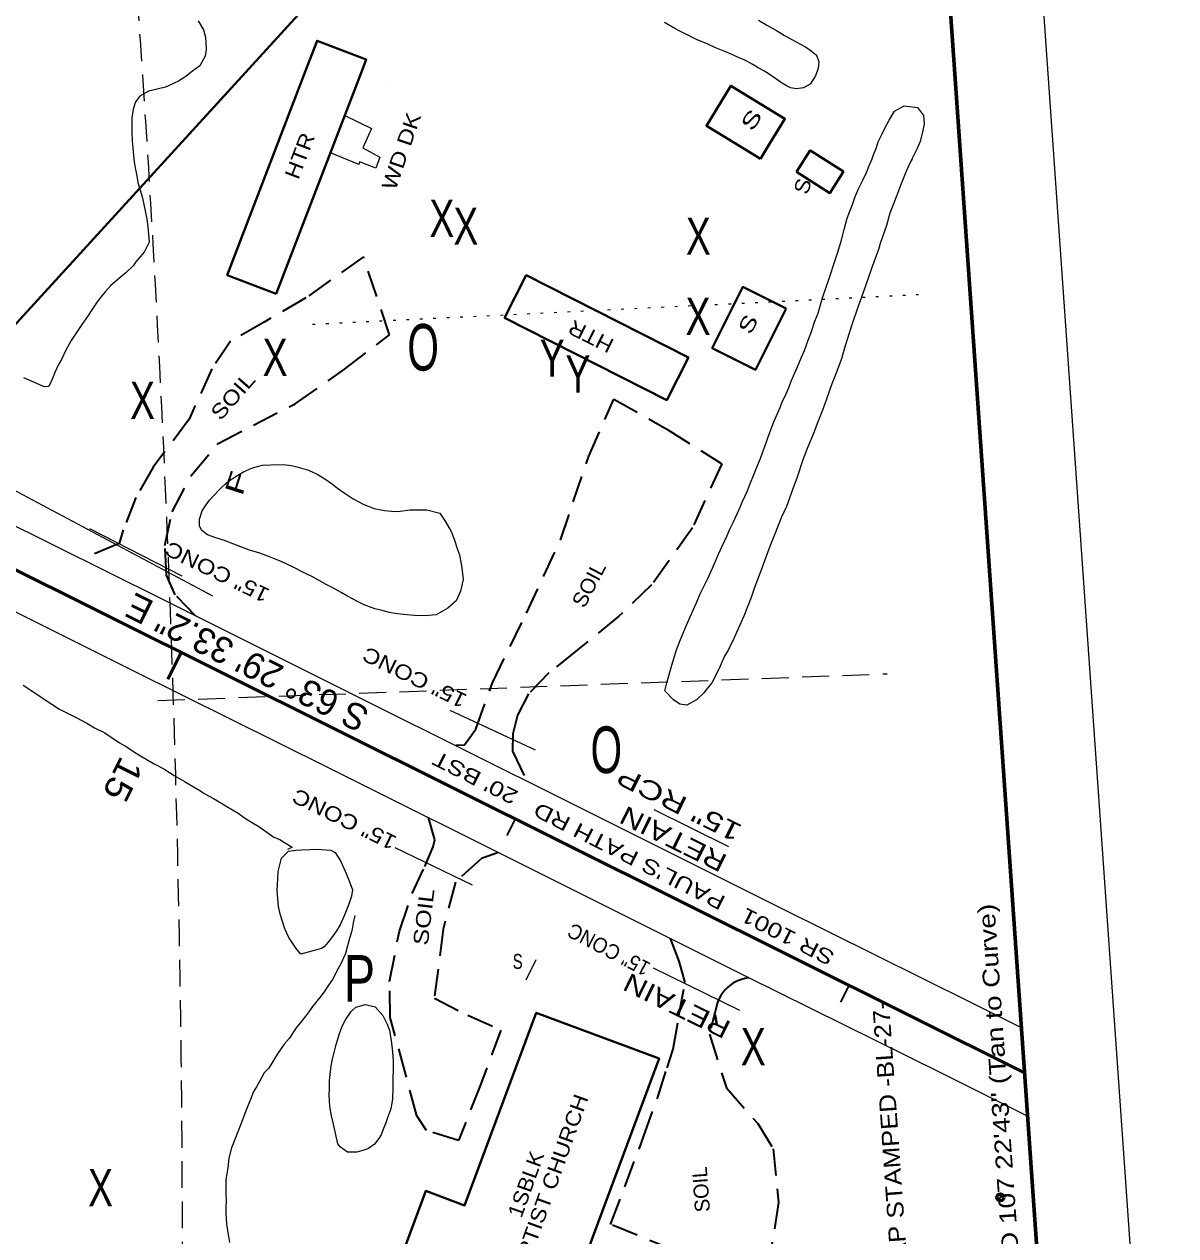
# Model space of a CAD drawing. Extents: x 2399800 to 2400616, y 567351 to 568869.
# Drawn here: x 2400216.3 to 2400525, y 568183.3 to 568508.2 of the extents above; entities that cross this region are included whole.
import ezdxf
from ezdxf.enums import TextEntityAlignment as Align

# ---------------------------------------------------------------- set-up
doc = ezdxf.new("R2010")
doc.units = 0
doc.header["$LTSCALE"] = 2.4
for name, pattern in [('DOTTED', [1.5, 0.3, -1.2]), ('LONG_DASHED', [7.5, 6, -1.5]), ('MEDIUM_DASHED', [4.5, 3, -1.5])]:
    doc.linetypes.add(name, pattern=pattern)
for name, color, linetype, lineweight in [('1', 7, 'Continuous', 40), ('11', 7, 'Continuous', 25), ('17', 7, 'MEDIUM_DASHED', 25), ('18', 7, 'Continuous', 13), ('26', 7, 'MEDIUM_DASHED', 35), ('3', 7, 'MEDIUM_DASHED', 35), ('38', 7, 'Continuous', 13), ('4', 7, 'Continuous', 35), ('6', 7, 'Continuous', 13), ('61', 7, 'Continuous', 40), ('62', 7, 'Continuous', 60), ('63', 7, 'Continuous', 35), ('8', 7, 'Continuous', 40)]:
    doc.layers.add(name, color=color, linetype=linetype, lineweight=lineweight)
for name, color, linetype in [('14', 7, 'Continuous'), ('23', 7, 'Continuous'), ('28', 7, 'Continuous'), ('5', 7, 'Continuous'), ('9', 7, 'Continuous')]:
    doc.layers.add(name, color=color, linetype=linetype)

msp = doc.modelspace()

# ---------------------------------------------------------------- linework, layer by layer
at = {"layer": '1'}
msp.add_line((2399965.144, 568485.991), (2400484.477, 568226.976), dxfattribs=at)
at = {"layer": '11', "linetype": 'DOTTED'}
msp.add_line((2400293.6, 568427.731), (2400455.985, 568435.717), dxfattribs=at)
at = {"layer": '11'}
for points in [[(2400262.9, 568509.114), (2400264.327, 568506.643), (2400264.905, 568504.664), (2400265.112, 568501.591), (2400265.074, 568501.373)], [(2400413.131, 568509.221), (2400415.538, 568507.84), (2400417.946, 568506.458), (2400420.064, 568505.191), (2400422.267, 568503.988), (2400424.18, 568502.9), (2400425.748, 568502.086), (2400427.287, 568501.047), (2400428.657, 568499.877), (2400429.339, 568498.113), (2400429.113, 568496.391), (2400428.39, 568494.354), (2400427.027, 568492.096), (2400425.224, 568491.115), (2400423.359, 568490.826), (2400421.722, 568491.117), (2400420.863, 568491.534), (2400419.314, 568492.498), (2400418.055, 568493.348), (2400415.957, 568494.765), (2400414.548, 568495.635), (2400413.064, 568496.515), (2400411.581, 568497.395), (2400409.444, 568498.512), (2400407.93, 568499.167), (2400405.773, 568500.135), (2400404.12, 568500.885), (2400401.439, 568501.922), (2400399.581, 568502.85), (2400396.546, 568504.086), (2400394.538, 568505.034), (2400392.036, 568506.275), (2400390.692, 568507.061), (2400387.93, 568508.641)], [(2400265.074, 568501.373), (2400264.782, 568499.655), (2400263.371, 568497.023), (2400261.518, 568495.667), (2400259.646, 568494.161), (2400257.653, 568492.9), (2400254.17, 568491.301), (2400252.285, 568490.862), (2400249.612, 568490.223), (2400247.311, 568488.926), (2400246.122, 568487.406), (2400245.483, 568485.434), (2400245.169, 568483.039), (2400245.119, 568480.914), (2400245.137, 568479.312), (2400245.272, 568476.858), (2400245.411, 568475.013), (2400245.702, 568472.005), (2400245.916, 568470.15), (2400246.481, 568467.488), (2400246.789, 568465.772), (2400247.467, 568463.399), (2400247.88, 568461.899), (2400248.283, 568460.323), (2400248.857, 568457.735), (2400249.146, 568455.87), (2400249.414, 568453.856), (2400249.793, 568449.77), (2400248.447, 568447.054), (2400246.203, 568444.455), (2400245.532, 568443.4), (2400243.62, 568441.596), (2400241.484, 568439.82), (2400239.507, 568438.099), (2400237.99, 568436.395), (2400236.641, 568434.82), (2400235.706, 568433.496), (2400234.205, 568431.333), (2400233.24, 568429.784), (2400231.739, 568427.621), (2400230.879, 568426.287), (2400228.895, 568423.349), (2400227.494, 568420.792), (2400226.252, 568418.29), (2400225.363, 568416.731), (2400224.499, 568414.789), (2400223.909, 568413.191), (2400222.866, 568411.044), (2400221.714, 568410.966), (2400219.837, 568411.745), (2400218.473, 568412.381), (2400216.241, 568413.358)], [(2400441.732, 568467.747), (2400442.046, 568468.429), (2400442.92, 568470.446), (2400443.595, 568472.109), (2400443.956, 568473.128), (2400444.755, 568475.155), (2400445.251, 568476.613), (2400446.294, 568478.76), (2400447.023, 568480.263), (2400448.151, 568482.476), (2400449.607, 568484.873), (2400452.153, 568486.291), (2400455.746, 568485.82), (2400457.372, 568483.704), (2400457.536, 568481.474), (2400457.152, 568479.697), (2400456.46, 568476.743), (2400455.576, 568474.65), (2400454.012, 568471.429), (2400452.855, 568468.992), (2400451.183, 568464.948), (2400450.127, 568462.117), (2400448.809, 568458.659)], [(2400388.052, 568329.476), (2400388.561, 568331.617), (2400389.862, 568336.319), (2400391.16, 568340.413), (2400392.206, 568343.169), (2400393.859, 568347.064), (2400394.837, 568349.296), (2400396.44, 568352.816), (2400397.541, 568355.413), (2400399.533, 568359.568), (2400400.814, 568362.369), (2400402.446, 568366.114), (2400403.414, 568368.272), (2400404.695, 568371.073), (2400405.549, 568372.941), (2400406.373, 568374.584), (2400407.436, 568376.881), (2400408.11, 568378.544), (2400408.86, 568380.196), (2400410.121, 568382.848), (2400410.825, 568384.736), (2400411.966, 568387.632), (2400412.661, 568389.444), (2400413.752, 568391.966), (2400414.333, 568393.488), (2400414.828, 568394.946), (2400416.018, 568398.216), (2400417.218, 568401.561), (2400418.196, 568403.794), (2400418.936, 568405.372), (2400419.516, 568406.894), (2400420.255, 568408.472), (2400421.338, 568410.919), (2400421.918, 568412.442), (2400422.905, 568414.749), (2400423.57, 568416.337), (2400424.672, 568418.933), (2400425.431, 568420.661), (2400426.488, 568423.492), (2400427.212, 568425.529), (2400428.222, 568428.594), (2400429.106, 568430.687), (2400430.254, 568434.799), (2400431.32, 568437.705), (2400431.93, 568439.453), (2400432.702, 568441.864), (2400433.123, 568443.331), (2400434.333, 568446.751), (2400435.288, 568449.976), (2400436.084, 568453.146), (2400436.936, 568456.156), (2400437.64, 568458.043), (2400438.334, 568459.856), (2400438.963, 568461.753), (2400439.846, 568463.845), (2400441.088, 568466.347), (2400442.046, 568468.429), (2400442.92, 568470.446), (2400443.595, 568472.109), (2400443.646, 568472.253)], [(2400454.291, 568472.003), (2400454.012, 568471.429), (2400452.855, 568468.992), (2400451.183, 568464.948), (2400450.127, 568462.117), (2400448.386, 568457.548), (2400447.421, 568454.248), (2400445.716, 568449.371), (2400445.275, 568447.753), (2400443.466, 568442.661), (2400442.37, 568439.531), (2400440.704, 568434.953), (2400439.638, 568432.047), (2400438.246, 568427.814), (2400437.349, 568425.038), (2400436.146, 568421.084), (2400435.419, 568418.439), (2400433.906, 568414.449), (2400432.794, 568411.778), (2400431.337, 568407.629), (2400430.271, 568404.723), (2400428.635, 568400.37), (2400428.054, 568398.847), (2400426.174, 568394.373), (2400425.023, 568391.402), (2400423.497, 568386.729), (2400422.326, 568383.609), (2400420.641, 568378.881), (2400419.246, 568375.79)], [(2400419.246, 568375.79), (2400417.441, 568371.306), (2400416.3, 568368.41), (2400414.767, 568364.271), (2400413.701, 568361.365), (2400412.084, 568357.161), (2400411.197, 568354.461), (2400409.248, 568349.463), (2400407.635, 568345.867), (2400406.657, 568343.635), (2400405.112, 568340.564), (2400404.034, 568338.726), (2400402.848, 568336.064), (2400402.118, 568334.561), (2400400.668, 568331.629), (2400399.121, 568329.7), (2400398.479, 568328.87), (2400396.483, 568327), (2400393.937, 568325.583), (2400392.075, 568325.903), (2400390.322, 568327.047), (2400388.052, 568329.476)], [(2400216.029, 568330.99), (2400218.881, 568329.1), (2400220.877, 568327.777), (2400223.729, 568325.886), (2400225.726, 568324.562), (2400230.231, 568322.316), (2400233.12, 568320.729), (2400235.135, 568319.557), (2400237.891, 568318.141), (2400239.602, 568317.007), (2400241.884, 568315.494), (2400243.614, 568314.512), (2400245.896, 568312.999), (2400247.474, 568312.035), (2400250.915, 568309.919), (2400252.226, 568309.296), (2400253.956, 568308.313), (2400255.249, 568307.538), (2400256.542, 568306.764), (2400259.413, 568305.025), (2400261.865, 568303.645), (2400263.595, 568302.663), (2400264.298, 568302.115), (2400265.743, 568301.321), (2400267.036, 568300.546), (2400269.203, 568299.356), (2400270.629, 568298.411), (2400273.652, 568296.654), (2400275.629, 568295.178), (2400277.207, 568294.215), (2400279.223, 568293.043), (2400281.352, 568291.549), (2400283.197, 568290.244), (2400284.812, 568289.584), (2400286.105, 568288.809), (2400288.101, 568287.486), (2400286.92, 568286.929)], [(2400304.894, 568269.196), (2400304.501, 568267.24), (2400304.089, 568265.132), (2400303.524, 568263.042), (2400302.979, 568261.105), (2400302.415, 568259.015), (2400301.981, 568257.989), (2400301.151, 568256.24), (2400300.357, 568254.796), (2400298.941, 568252.04), (2400297.825, 568250.48), (2400296.691, 568248.769), (2400295.575, 568247.21), (2400293.589, 568244.832), (2400292.454, 568243.12), (2400290.449, 568240.591), (2400289.181, 568239.05), (2400287.291, 568236.198), (2400286.023, 568234.657), (2400284.169, 568232.108), (2400283.206, 568230.53), (2400281.845, 568228.23), (2400280.615, 568226.993), (2400279.424, 568224.826), (2400278.612, 568223.23), (2400277.667, 568221.804), (2400277.178, 568220.322), (2400275.668, 568216.806), (2400274.519, 568213.709), (2400273.388, 568210.764), (2400272.275, 568207.971), (2400271.841, 568206.945), (2400271.184, 568204.096), (2400270.868, 568201.514), (2400270.4, 568198.95), (2400270.308, 568198.191), (2400270.373, 568194.945), (2400270.398, 568192.629), (2400270.364, 568191.091), (2400270.312, 568189.402), (2400270.567, 568186.442), (2400270.818, 568184.715), (2400271.357, 568181.566)]]:
    msp.add_lwpolyline(points, dxfattribs=at)
for points in [[(2400327.743, 568377.047), (2400329.144, 568374.96), (2400330.757, 568372.16), (2400331.55, 568370.076), (2400332.488, 568367.365), (2400332.985, 568365.929), (2400333.592, 568362.423), (2400333.948, 568359.331), (2400333.227, 568356.152), (2400332.05, 568353.565), (2400329.895, 568351.64), (2400326.691, 568349.851), (2400323.758, 568349.551), (2400320.8, 568349.634), (2400317.946, 568349.932), (2400315.691, 568350.151), (2400314.203, 568350.422), (2400311.922, 568351.026), (2400310.305, 568351.466), (2400307.474, 568352.522), (2400305.606, 568353.376), (2400302.974, 568354.787), (2400301.276, 568355.771), (2400298.868, 568357.152), (2400297.225, 568357.977), (2400293.744, 568359.88), (2400291.391, 568361.102), (2400288.395, 568362.637), (2400286.527, 568363.49), (2400285.164, 568364.126), (2400282.053, 568365.371), (2400279.437, 568366.323), (2400276.726, 568367.135), (2400275.568, 568367.591), (2400272.522, 568368.752), (2400269.692, 568369.808), (2400267.645, 568370.457), (2400265.468, 568371.275), (2400263.939, 568372.389), (2400263.263, 568373.62), (2400263.274, 568375.446), (2400264.027, 568377.707), (2400265.076, 568379.321), (2400266.001, 568380.57), (2400267.066, 568381.725), (2400268.743, 568383.485), (2400270.739, 568385.355), (2400273.09, 568387.027), (2400275.063, 568388.138), (2400277.485, 568389.191), (2400280.167, 568389.906), (2400282.397, 568390.07), (2400285.749, 568390.088), (2400287.93, 568389.878), (2400289.407, 568389.532), (2400292.482, 568388.596), (2400294.854, 568387.524), (2400296.897, 568386.267), (2400298.921, 568384.859), (2400300.3, 568383.765), (2400302.044, 568382.547), (2400304.497, 568380.931), (2400307.344, 568379.416), (2400310.09, 568378.294), (2400312.84, 568377.782), (2400315.704, 568377.559), (2400317.081, 568377.606), (2400319.639, 568377.956), (2400321.699, 568377.991), (2400324.209, 568377.967)], [(2400290.434, 568258.805), (2400289.158, 568260.349), (2400287.205, 568263.286), (2400286.183, 568265.646), (2400285.007, 568269.259), (2400284.45, 568271.64), (2400284.116, 568275.843), (2400284.288, 568279.137), (2400284.359, 568280.978), (2400285.26, 568284.568), (2400287.106, 568286.424), (2400289.07, 568286.723), (2400290.617, 568286.765), (2400292.942, 568286.866), (2400294.65, 568286.966), (2400298.475, 568286.729), (2400299.625, 568286.049), (2400301.055, 568283.87), (2400302.334, 568281.092), (2400303.404, 568278.495), (2400304.264, 568276.077), (2400304.059, 568274.406), (2400303.334, 568272.259), (2400302.1, 568269.096), (2400300.958, 568266.691), (2400299.994, 568265.113), (2400298.68, 568263.193), (2400297.771, 568262.071), (2400296.693, 568260.815), (2400296.02, 568260.358)], [(2400299.204, 568213.285), (2400298.705, 568215.505), (2400298.233, 568217.952), (2400298.124, 568219.584), (2400298.083, 568221.131), (2400298.126, 568222.744), (2400298.167, 568224.975), (2400298.286, 568226.579), (2400298.575, 568228.933), (2400298.94, 568230.662), (2400299.842, 568234.252), (2400300.858, 568237.519), (2400301.592, 568239.742), (2400302.395, 568241.262), (2400303.974, 568243.459), (2400305.195, 568244.62), (2400307.822, 568245.301), (2400310.368, 568244.681), (2400312.395, 568242.351), (2400313.578, 568240.049), (2400314.228, 568238.427), (2400314.653, 568235.6), (2400314.943, 568233.561), (2400315.179, 568230.448), (2400315.223, 568228.285), (2400315.146, 568225.133), (2400315.15, 568223.283), (2400315.055, 568219.98), (2400314.578, 568217.34), (2400313.777, 568215.203), (2400313.278, 568213.645), (2400312.627, 568212.106), (2400311.958, 568210.414), (2400311.372, 568209.407), (2400310.18, 568207.857), (2400308.579, 568206.742), (2400307.365, 568206.274), (2400305.45, 568205.738), (2400302.982, 568205.731), (2400301.071, 568207.121), (2400300.405, 568207.973)]]:
    msp.add_lwpolyline(points, close=True, dxfattribs=at)
at = {"layer": '17'}
msp.add_line((2400252.161, 568326.829), (2400447.665, 568334.013), dxfattribs=at)
msp.add_arc((2395446.846, 568174.368), 4811.888, 358.84472, 7.18511, dxfattribs=at)
at = {"layer": '18'}
msp.add_line((2400086.216, 568451.054), (2400266.761, 568354.939), dxfattribs=at)
at = {"layer": '26', "linetype": 'LONG_DASHED'}
for p in [(2400314.564, 568493.073), (2400314.566, 568493.081)]:
    msp.add_line(p, (2400314.566, 568493.081), dxfattribs=at)
at = {"layer": '3', "linetype": 'Continuous', "lineweight": 60}
msp.add_line((2400258.391, 568339.736), (2400254.82, 568332.577), dxfattribs=at)
at = {"layer": '3', "linetype": 'Continuous', "lineweight": 25}
for points in [[(2400483.629, 568239.104), (2400470.246, 568245.798), (2400419.343, 568271.108), (2400362.072, 568299.673), (2400308.009, 568326.642), (2400253.449, 568353.932), (2400194.927, 568382.951), (2400136.831, 568411.76), (2400076.265, 568441.964), (2400023.623, 568468.434), (2399965.535, 568497.344), (2399964.308, 568497.949)], [(2400485.284, 568215.439), (2400462, 568226.988), (2400409.841, 568252.853), (2400354.423, 568280.585), (2400297.876, 568308.829), (2400245.542, 568334.846), (2400186.098, 568364.488), (2400128.133, 568393.345), (2400067.555, 568423.559), (2400013.737, 568450.439), (2399965.96, 568474.329)]]:
    msp.add_lwpolyline(points, dxfattribs=at)
at = {"layer": '3'}
for points in [[(2400262.208, 568349.574), (2400256.772, 568355.159), (2400254.416, 568360.417), (2400254.014, 568368.387), (2400255.959, 568377.421), (2400261.13, 568387.25), (2400268.26, 568395.757), (2400277.737, 568400.682), (2400288.914, 568406.374), (2400302.163, 568415.677), (2400314.26, 568424.904), (2400307.249, 568445.77), (2400291.799, 568434.775), (2400280.599, 568428.325), (2400271.626, 568423.182), (2400266.619, 568415.767), (2400260.508, 568402.255), (2400250.909, 568389.427), (2400246.188, 568381.291), (2400242.84, 568372.593), (2400241.751, 568368.929), (2400231.848, 568364.821)], [(2400332.041, 568314.84), (2400334.345, 568314.995), (2400337.329, 568319.172), (2400341.851, 568331.598), (2400350.923, 568350.281), (2400360.038, 568369.872), (2400367.626, 568392.327), (2400374.356, 568407.662), (2400388.532, 568399.637), (2400403.299, 568390.317), (2400395.415, 568373.154), (2400384.499, 568357.834), (2400375.714, 568349.468), (2400364.629, 568340.414), (2400356.97, 568334.261), (2400351.516, 568328.657), (2400348.55, 568322.878), (2400347.284, 568317.867), (2400347.21, 568313.233), (2400351.163, 568305.115)], [(2400343.425, 568286.079), (2400338.908, 568284.448), (2400331.913, 568278.131), (2400328.589, 568265.547), (2400326.241, 568247.049), (2400335.231, 568242.445), (2400344.075, 568238.469), (2400338.575, 568223.811), (2400332.737, 568208.892), (2400324.101, 568211.546), (2400321.568, 568215.456), (2400318.6, 568226.505), (2400314.365, 568241.83), (2400314.263, 568251.512), (2400316.872, 568265.027), (2400320.322, 568275.082), (2400323.708, 568282.328), (2400325.921, 568287.596), (2400326.4, 568289.513), (2400324.683, 568295.439)], [(2400390.638, 568179.356), (2400373.461, 568186.39), (2400382.339, 568209.818), (2400386.117, 568220.533), (2400388.621, 568228.398), (2400390.306, 568233.356), (2400391.791, 568242.348), (2400393.496, 568251.236), (2400391.886, 568256.983), (2400389.586, 568262.989)], [(2400410.59, 568252.482), (2400410.339, 568252.461), (2400409.458, 568252.307), (2400408.595, 568252.076), (2400407.754, 568251.768), (2400406.945, 568251.387), (2400406.173, 568250.934), (2400405.445, 568250.414), (2400404.765, 568249.832), (2400404.139, 568249.191), (2400403.573, 568248.497), (2400403.071, 568247.755), (2400402.637, 568246.971), (2400402.274, 568246.151), (2400402.165, 568245.858), (2400399.967, 568237.339), (2400404.532, 568222.983), (2400412.918, 568213.4), (2400417.102, 568206.645), (2400418.507, 568192.289), (2400416.388, 568178.75)]]:
    msp.add_lwpolyline(points, dxfattribs=at)
at = {"layer": '38'}
msp.add_line((2399965.144, 568485.991), (2400484.477, 568226.976), dxfattribs=at)
at = {"layer": '4'}
for p, q in [((2400347.878, 568295.105), (2400345.646, 568290.63)), ((2400437.366, 568250.473), (2400435.134, 568245.999))]:
    msp.add_line(p, q, dxfattribs=at)
at = {"layer": '6'}
for p, q in [((2400258.66, 568360.155), (2400233.931, 568372.892)), ((2400353.395, 568313.493), (2400330.494, 568324.157)), ((2400405.196, 568287.654), (2400385.211, 568297.575)), ((2400336.483, 568277.327), (2400315.738, 568287.341)), ((2400408.15, 568243.739), (2400385.02, 568255.047))]:
    msp.add_line(p, q, dxfattribs=at)
at = {"layer": '61'}
msp.add_line((2400340.726, 568566.615), (2400172.663, 568382.492), dxfattribs=at)
at = {"layer": '62'}
msp.add_line((2399965.144, 568485.991), (2400484.477, 568226.976), dxfattribs=at)
at = {"layer": '63', "lineweight": 13}
msp.add_line((2400524.992, 568005.982), (2400465.699, 568853.912), dxfattribs=at)
at = {"layer": '63', "lineweight": 60}
msp.add_line((2400442.155, 568832.216), (2400498.188, 568030.909), dxfattribs=at)
at = {"layer": '63', "lineweight": 53}
msp.add_circle((2400477.989, 568193.629), 0.919, dxfattribs=at)
at = {"layer": '8'}
for p, q in [((2400283.881, 568435.851), (2400306.348, 568494.458)), ((2400413.639, 568472.059), (2400403.731, 568478.144)), ((2400416.103, 568476.071), (2400413.639, 568472.059)), ((2400426.927, 568474.258), (2400423.334, 568468.598))]:
    msp.add_line(p, q, dxfattribs=at)
at = {"layer": '8', "lineweight": 25}
msp.add_line((2400350.865, 568251.97), (2400353.557, 568257.404), dxfattribs=at)
at = {"layer": '8'}
for points in [[(2400306.348, 568494.458), (2400307.967, 568498.68), (2400294.804, 568503.726), (2400292.163, 568496.835)], [(2400292.163, 568496.835), (2400270.718, 568440.897), (2400283.881, 568435.851)], [(2400403.731, 568478.144), (2400399.172, 568480.944), (2400405.757, 568491.666), (2400420.224, 568482.781), (2400416.103, 568476.071)], [(2400423.334, 568468.598), (2400432.272, 568462.923), (2400435.915, 568468.662), (2400427.164, 568474.218)], [(2400427.164, 568474.218), (2400426.977, 568474.336), (2400426.927, 568474.258)]]:
    msp.add_lwpolyline(points, dxfattribs=at)
at = {"layer": '8', "lineweight": 25}
msp.add_lwpolyline([(2400302.21, 568483.662), (2400309.368, 568480.26), (2400307.09, 568475.076), (2400311.626, 568472.502), (2400310.559, 568469.596), (2400306.215, 568471.308), (2400305.968, 568470.579), (2400298.383, 568473.68)], dxfattribs=at)
at = {"layer": '8'}
for points in [[(2400345.073, 568429.43), (2400388.565, 568407.382), (2400394.357, 568418.807), (2400350.865, 568440.855)], [(2400420.552, 568431.929), (2400412.352, 568415.532), (2400400.737, 568421.34), (2400408.937, 568437.738)], [(2400377.037, 568144.88), (2400313.925, 568168.365), (2400323.96, 568195.332), (2400334.338, 568191.47), (2400353.556, 568243.115), (2400386.515, 568230.85), (2400367.304, 568179.225), (2400387.079, 568171.866)]]:
    msp.add_lwpolyline(points, close=True, dxfattribs=at)

# ---------------------------------------------------------------- texts
at = {"layer": '11', "width": 0.75}
for s, p in [('X', (2400328.262, 568451.091)), ('X', (2400334.692, 568449.03)), ('X', (2400397.001, 568446.346)), ('X', (2400396.929, 568424.885)), ('X', (2400283.563, 568413.856)), ('Y', (2400357.844, 568413.638)), ('Y', (2400364.748, 568409.383)), ('X', (2400248.015, 568402.297)), ('X', (2400411.742, 568229)), ('X', (2400236.76, 568191.203))]:
    msp.add_text(s, height=10, dxfattribs=at).set_placement(p, align=Align.CENTER)
at = {"layer": '14', "width": 0.75}
msp.add_text('P', height=12.5, dxfattribs=at).set_placement((2400306.163, 568246.09), align=Align.CENTER)
at = {"layer": '23'}
for s, rotation, width, p in [('SOIL', 48.797, 1.2, (2400273.74, 568407.155)), ('SOIL', 62.305, 1.05, (2400369.445, 568357.044)), ("SR 1001   PAUL'S PATH RD   20' BST", 153.046, 1.3, (2400380.551, 568286.305)), ('SOIL', 83.17, 1.25, (2400325.393, 568268.578))]:
    msp.add_text(s, height=4, rotation=rotation, dxfattribs=dict(at, width=width)).set_placement(p, align=Align.CENTER)
msp.add_text('SOIL', height=4, rotation=94.208, dxfattribs=at).set_placement((2400399.708, 568195.877), align=Align.CENTER)
at = {"layer": '26'}
for s, height, rotation, width, p in [('F', 5, 72.078, 1.5, (2400275.648, 568384.357)), ('15" CONC', 4, 153.938, 1.2, (2400268.914, 568363.097)), ('15" CONC', 4, 153.938, 1.2, (2400321.812, 568334.808)), ('15" CONC', 4, 153.938, 1.2, (2400302.984, 568296.791)), ('15" CONC', 4, 152.417, 0.95, (2400373.92, 568261.815))]:
    msp.add_text(s, height=height, rotation=rotation, dxfattribs=dict(at, width=width)).set_placement(p, align=Align.CENTER)
at = {"layer": '28'}
for s, rotation, width, p in [('WD DK', 71.094, 1.2, (2400319.276, 568473.479)), ('S', 56.294, 1.5, (2400412.904, 568481.431)), ('HTR', 68.951, 1.15, (2400292.034, 568472.186)), ('S', 72.111, 1.1, (2400426.873, 568464.134)), ('HTR', 153.449, 1.15, (2400369.098, 568426.233)), ('S', 61.914, 1.35, (2400412.114, 568426.824)), ('BAPTIST CHURCH', 70.222, 1.15, (2400358.494, 568194.936)), ('1SBLK', 70.222, 1.1, (2400352.672, 568196.478))]:
    msp.add_text(s, height=4, rotation=rotation, dxfattribs=dict(at, width=width)).set_placement(p, align=Align.CENTER)
at = {"layer": '28', "width": 0.75}
for p in [(2400348.58, 568254.889), (2400348.596, 568254.889)]:
    msp.add_text('S', height=4, dxfattribs=at).set_placement(p, align=Align.CENTER)
at = {"layer": '5'}
for s, rotation, width, p in [('15" RCP', 153.597, 1.4, (2400409.129, 568293.193)), ('RETAIN', 153.597, 1.25, (2400405.127, 568285.132)), ('RETAIN', 153.945, 1.25, (2400406.114, 568240.482))]:
    msp.add_text(s, height=5, rotation=rotation, dxfattribs=dict(at, width=width)).set_placement(p)
at = {"layer": '61'}
msp.add_text('S 63° 29\' 33.2" E', height=7, rotation=153.493, dxfattribs=at).set_placement((2400277.604, 568340.169), align=Align.CENTER)
at = {"layer": '61', "width": 1.1}
msp.add_text('15', height=7, rotation=243.493, dxfattribs=at).set_placement((2400239.669, 568307.171), align=Align.CENTER)
at = {"layer": '63'}
for s, width, p in [('SKEW ANGLE FOR BENTS 110 41\'38" AND 107 22\'43" (Tan to Curve)', 1.25, (2400493, 568034.493)), ('NCDOT TRAVERSE STATION REBAR AND CAP STAMPED -BL-27-', 1.15, (2400463.073, 568032.4))]:
    msp.add_text(s, height=4.5, rotation=94, dxfattribs=dict(at, width=width)).set_placement(p)
at = {"layer": '9', "width": 0.65}
for p in [(2400323.239, 568415.3), (2400372.348, 568307.39)]:
    msp.add_text('O', height=12.5, dxfattribs=at).set_placement(p, align=Align.CENTER)

doc.saveas('drawing.dxf')
